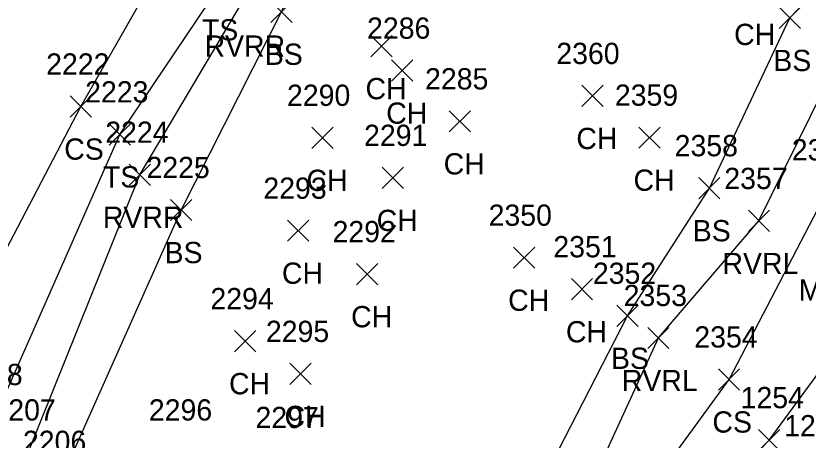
# Model space of a CAD drawing. Extents: x 1459992 to 1461532, y 647785 to 648535.
# Drawn here: x 1461256.6 to 1461331.1, y 648118.2 to 648158.1 of the extents above; entities that cross this region are included whole.
import ezdxf

# ---------------------------------------------------------------- set-up
doc = ezdxf.new("R2010")
doc.units = 0
for name, color, linetype in [('L_A', 7, 'Continuous'), ('L_C', 7, 'Continuous'), ('L_I', 7, 'Continuous'), ('L_TIC', 7, 'Continuous'), ('LAWE', 7, 'Continuous'), ('LELB', 7, 'Continuous')]:
    doc.layers.add(name, color=color, linetype=linetype)

msp = doc.modelspace()

# ---------------------------------------------------------------- linework, layer by layer
at = {"layer": 'L_TIC'}
for points in [[(1461280.565, 648157.473), (1461282.565, 648159.473)], [(1461282.565, 648157.473), (1461280.565, 648159.473)], [(1461328.36, 648156.887), (1461330.36, 648158.887)], [(1461330.36, 648156.887), (1461328.36, 648158.887)], [(1461289.984, 648154.239), (1461291.984, 648156.239)], [(1461291.984, 648154.239), (1461289.984, 648156.239)], [(1461291.929, 648151.933), (1461293.929, 648153.933)], [(1461293.929, 648151.933), (1461291.929, 648153.933)], [(1461309.798, 648149.552), (1461311.798, 648151.552)], [(1461311.798, 648149.552), (1461309.798, 648151.552)], [(1461261.717, 648148.553), (1461263.717, 648150.553)], [(1461263.717, 648148.553), (1461261.717, 648150.553)], [(1461297.329, 648147.163), (1461299.329, 648149.163)], [(1461299.329, 648147.163), (1461297.329, 648149.163)], [(1461265.382, 648145.936), (1461267.382, 648147.936)], [(1461267.382, 648145.936), (1461265.382, 648147.936)], [(1461284.439, 648145.614), (1461286.439, 648147.614)], [(1461286.439, 648145.614), (1461284.439, 648147.614)], [(1461315.173, 648145.628), (1461317.173, 648147.628)], [(1461317.173, 648145.628), (1461315.173, 648147.628)], [(1461267.272, 648142.142), (1461269.272, 648144.142)], [(1461269.272, 648142.142), (1461267.272, 648144.142)], [(1461291.031, 648141.845), (1461293.031, 648143.845)], [(1461293.031, 648141.845), (1461291.031, 648143.845)], [(1461320.787, 648140.876), (1461322.787, 648142.876)], [(1461322.787, 648140.876), (1461320.787, 648142.876)], [(1461271.144, 648138.82), (1461273.144, 648140.82)], [(1461273.144, 648138.82), (1461271.144, 648140.82)], [(1461325.453, 648137.792), (1461327.453, 648139.792)], [(1461327.453, 648137.792), (1461325.453, 648139.792)], [(1461282.129, 648136.877), (1461284.129, 648138.877)], [(1461284.129, 648136.877), (1461282.129, 648138.877)], [(1461303.386, 648134.335), (1461305.386, 648136.335)], [(1461305.386, 648134.335), (1461303.386, 648136.335)], [(1461288.632, 648132.79), (1461290.632, 648134.79)], [(1461290.632, 648132.79), (1461288.632, 648134.79)], [(1461308.82, 648131.369), (1461310.82, 648133.369)], [(1461310.82, 648131.369), (1461308.82, 648133.369)], [(1461313.102, 648128.874), (1461315.102, 648130.874)], [(1461315.102, 648128.874), (1461313.102, 648130.874)], [(1461277.155, 648126.485), (1461279.155, 648128.485)], [(1461279.155, 648126.485), (1461277.155, 648128.485)], [(1461315.994, 648126.784), (1461317.994, 648128.784)], [(1461317.994, 648126.784), (1461315.994, 648128.784)], [(1461282.37, 648123.405), (1461284.37, 648125.405)], [(1461284.37, 648123.405), (1461282.37, 648125.405)], [(1461322.636, 648122.883), (1461324.636, 648124.883)], [(1461324.636, 648122.883), (1461322.636, 648124.883)], [(1461326.419, 648117.176), (1461328.419, 648119.176)], [(1461328.419, 648117.176), (1461326.419, 648119.176)]]:
    msp.add_lwpolyline(points, dxfattribs=at)
at = {"layer": 'LAWE'}
for points in [[(1461220.159, 648021.615), (1461235.47, 648039.294), (1461252.966, 648048.327), (1461267.663, 648064.216), (1461276.22, 648071.524), (1461288.833, 648087.698), (1461307.75, 648107.551), (1461316.994, 648127.784), (1461326.453, 648138.792), (1461334.868, 648155.88), (1461340.573, 648163.303), (1461349.799, 648178.335), (1461354.706, 648199.541), (1461353.8, 648220.98), (1461352.341, 648246.452), (1461354.078, 648262.219), (1461358.254, 648276.136), (1461371.394, 648295.376), (1461381.983, 648319.016), (1461394.178, 648330.617), (1461418.251, 648335.818), (1461440.86, 648338.789), (1461464.612, 648337.5), (1461486.388, 648342.471)], [(1461175.582, 648047.692), (1461190.072, 648060.795), (1461210.579, 648076.7), (1461225.386, 648087.992), (1461242.999, 648102.806), (1461257.751, 648117.016), (1461268.272, 648143.142), (1461277.829, 648159.24), (1461282.957, 648175.462), (1461289.558, 648186.996), (1461293.87, 648195.588), (1461292.337, 648203.444)]]:
    msp.add_lwpolyline(points, dxfattribs=at)
at = {"layer": 'LELB'}
for points in [[(1461216.735, 648025.379), (1461232.531, 648043.682), (1461249.111, 648052.696), (1461265.41, 648068.573), (1461273.176, 648074.771), (1461285.769, 648090.042), (1461304.003, 648110.191), (1461314.102, 648129.874), (1461321.787, 648141.876), (1461329.36, 648157.887), (1461338.075, 648167.022), (1461343.94, 648182.363), (1461347.487, 648202.693), (1461348.844, 648222.98), (1461349.522, 648245.94), (1461349.946, 648262.877), (1461353.497, 648277.365), (1461366.77, 648299.226), (1461380.277, 648319.065), (1461391.623, 648332.953), (1461418.599, 648338.961), (1461441.306, 648340.652), (1461465.695, 648340.733), (1461485.923, 648346.235)], [(1461181.212, 648043.592), (1461191.79, 648059.054), (1461212.855, 648073.874), (1461227.371, 648085.596), (1461246.178, 648099.024), (1461260.669, 648114.058), (1461272.144, 648139.82), (1461281.565, 648158.473), (1461288.148, 648173.487), (1461292.193, 648183.75), (1461298.563, 648193.295), (1461300.86, 648204.122), (1461298.63, 648210.737)], [(1461171.661, 648050.372), (1461189.066, 648062.585), (1461207.829, 648079.497), (1461223.93, 648090.745), (1461240.199, 648105.174), (1461254.637, 648120.348), (1461266.382, 648146.936), (1461275.686, 648160.772), (1461281.846, 648176.9), (1461284.459, 648191.448), (1461287.846, 648196.16)], [(1461162.415, 648057.492), (1461184.81, 648068.652), (1461202.033, 648084.354), (1461220.873, 648096.789), (1461234.917, 648111.93), (1461250.129, 648125.473), (1461262.717, 648149.553), (1461271.471, 648164.918), (1461276.289, 648181.15), (1461284.459, 648191.448)], [(1461222.105, 648019.642), (1461239.41, 648035.454), (1461252.966, 648048.327), (1461269.635, 648062.753), (1461277.559, 648070.159), (1461291.696, 648084.237), (1461310.278, 648105.504), (1461323.636, 648123.883), (1461332.795, 648141.481), (1461336.745, 648150.816)], [(1461226.023, 648017.252), (1461244.712, 648034.329), (1461263.294, 648051.101), (1461279.296, 648066.077), (1461297.191, 648082.439), (1461309.728, 648099.716), (1461327.419, 648118.176), (1461335.223, 648128.809), (1461339.468, 648139.304)]]:
    msp.add_lwpolyline(points, dxfattribs=at)

# ---------------------------------------------------------------- texts
at = {"layer": 'L_A'}
for s, p in [('TS', (1461274.096, 648155.772)), ('CH', (1461324.117, 648155.341)), ('RVRR', (1461274.341, 648154.24)), ('BS', (1461280.006, 648153.473)), ('BS', (1461327.8, 648152.887)), ('CH', (1461289.473, 648150.239)), ('CH', (1461291.418, 648147.933)), ('CH', (1461309.286, 648145.552)), ('CS', (1461261.158, 648144.553)), ('CH', (1461296.817, 648143.163)), ('TS', (1461264.791, 648141.936)), ('CH', (1461283.927, 648141.614)), ('CH', (1461314.662, 648141.628)), ('RVRR', (1461264.784, 648138.142)), ('CH', (1461290.52, 648137.845)), ('BS', (1461320.228, 648136.876)), ('BS', (1461270.585, 648134.82)), ('RVRL', (1461323.02, 648133.792)), ('CH', (1461281.618, 648132.877)), ('CH', (1461302.875, 648130.335)), ('CH', (1461288.12, 648128.79)), ('CH', (1461308.308, 648127.369)), ('BS', (1461312.543, 648124.874)), ('CH', (1461276.644, 648122.485)), ('RVRL', (1461313.561, 648122.784)), ('CH', (1461281.858, 648119.405)), ('CS', (1461322.077, 648118.883))]:
    msp.add_text(s, height=2, dxfattribs=at).set_placement(p)
at = {"layer": 'L_C'}
msp.add_text('M.WILLOW', height=2, dxfattribs=at).set_placement((1461330.178, 648131.3))
at = {"layer": 'L_I'}
for s, p in [('2286', (1461289.615, 648155.933)), ('2360', (1461307.404, 648153.552)), ('2222', (1461259.457, 648152.553)), ('2285', (1461295.069, 648151.163)), ('2223', (1461263.122, 648149.936)), ('2290', (1461282.093, 648149.614)), ('2359', (1461312.906, 648149.628)), ('2224', (1461265.012, 648146.142)), ('2291', (1461289.338, 648145.845)), ('2358', (1461318.527, 648144.876)), ('2355', (1461329.535, 648144.481)), ('2225', (1461268.884, 648142.82)), ('2357', (1461323.193, 648141.792)), ('2293', (1461279.87, 648140.877)), ('2350', (1461301.04, 648138.335)), ('2292', (1461286.372, 648136.79)), ('2351', (1461307.127, 648135.369)), ('2352', (1461310.842, 648132.874)), ('2353', (1461313.734, 648130.784)), ('2294', (1461274.896, 648130.485)), ('2295', (1461280.11, 648127.405)), ('2354', (1461320.376, 648126.883)), ('2208', (1461251.299, 648123.348)), ('1254', (1461324.726, 648121.176)), ('2207', (1461254.413, 648120.016)), ('2296', (1461269.11, 648120.017)), ('2297', (1461279.131, 648119.302)), ('1255', (1461328.818, 648118.53)), ('2206', (1461257.275, 648117.058))]:
    msp.add_text(s, height=2, dxfattribs=at).set_placement(p)

doc.saveas('drawing.dxf')
